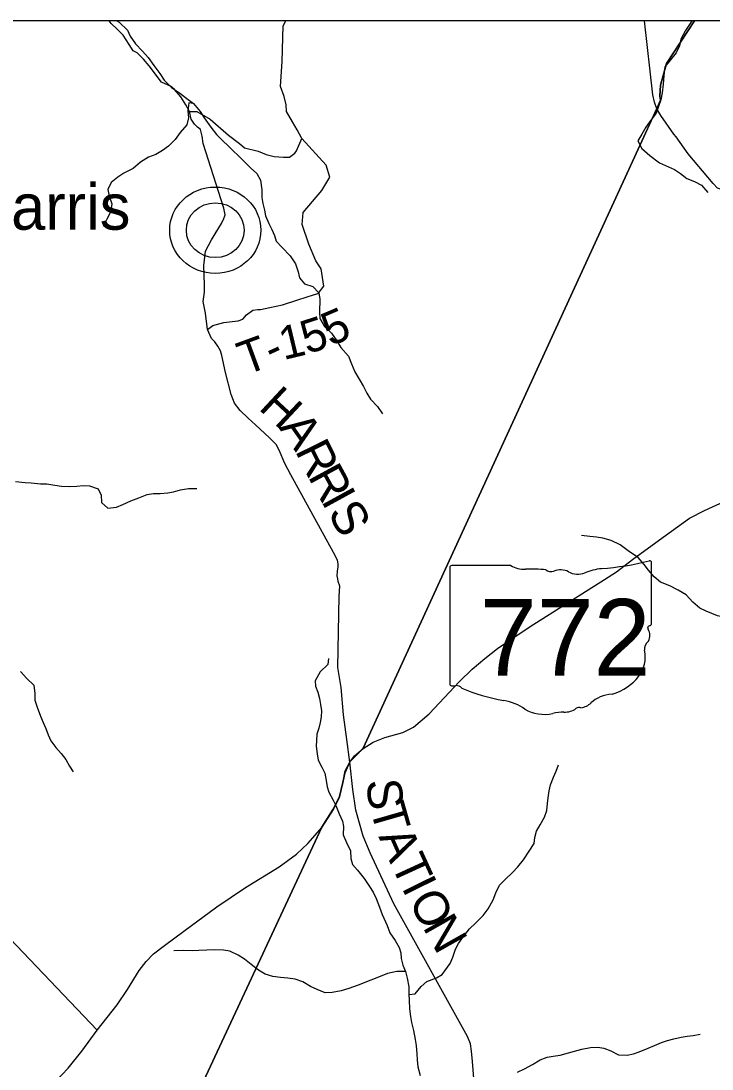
# Model space of a CAD drawing. Extents: x -139 to 835, y 0 to 440.
# Drawn here: x 168.3 to 206.1, y 344.1 to 401.5 of the extents above; entities that cross this region are included whole.
import ezdxf

# ---------------------------------------------------------------- set-up
doc = ezdxf.new("R2010")
doc.units = 0
for name, color, linetype in [('GM_X_County_Text', 7, 'Continuous'), ('GM_X_Minor_River', 7, 'Continuous'), ('GM_X_State_Location', 7, 'Continuous'), ('GM_X_State_Route', 7, 'Continuous'), ('GM_X_State_Shield', 7, 'Continuous'), ('GM_X_Township_Road', 7, 'Continuous'), ('GM_X_Township_Road_Text', 7, 'Continuous'), ('GM_X_Unincorporated', 7, 'Continuous'), ('GM_X_Unincorporated_Location', 7, 'Continuous'), ('GM_X_Unincorporated_Text', 7, 'Continuous'), ('SH_Cut_Line', 7, 'Continuous')]:
    doc.layers.add(name, color=color, linetype=linetype)

msp = doc.modelspace()

# ---------------------------------------------------------------- linework, layer by layer
at = {"layer": 'GM_X_County_Text'}
for points in [[(205.139, 401.486), (87.298, 401.486), (90.116, 391.109), (100.145, 354.177), (105.67, 333.828), (158.444, 330.1), (160.688, 329.921), (171.559, 329.033), (172.321, 330.669), (184.767, 357.384), (185.383, 358.364), (185.729, 359.048), (185.902, 359.821), (186.018, 360.334), (186.292, 360.95), (186.616, 361.275), (187.014, 361.689), (203.078, 396.689), (203.294, 397.153), (203.246, 397.371), (203.278, 397.973), (203.623, 399.152)], [(295.458, 319.381), (295.458, 401.486), (205.139, 401.486), (203.623, 399.152), (203.278, 397.973), (203.246, 397.371), (203.294, 397.153), (203.078, 396.689), (187.014, 361.689), (186.616, 361.275), (186.292, 360.95), (186.018, 360.334), (185.902, 359.821), (185.729, 359.048), (185.383, 358.364), (184.767, 357.384), (172.321, 330.669), (171.559, 329.033), (177.155, 328.576), (194.287, 327.176), (207.436, 326.102), (228.151, 324.569), (267.909, 321.538)]]:
    msp.add_lwpolyline(points, close=True, dxfattribs=at)
at = {"layer": 'GM_X_Minor_River'}
for points in [[(173.541, 401.486), (173.671, 401.418), (174.122, 400.991), (174.283, 400.663), (174.569, 400.238), (174.944, 399.836), (175.269, 399.483), (175.568, 399.057), (175.905, 398.607), (176.141, 398.243), (176.542, 397.841), (176.969, 397.546), (177.308, 397.301), (177.747, 396.971), (178.109, 396.533), (178.333, 396.192), (178.694, 395.67), (178.993, 395.269), (179.319, 394.939), (179.657, 394.634), (180.433, 393.878), (180.859, 393.451), (181.197, 393.146), (181.408, 392.782), (181.477, 392.25), (181.472, 391.828), (181.531, 391.49), (181.616, 391.14), (181.688, 390.825), (181.86, 390.401), (182.033, 390.074), (182.169, 389.747), (182.254, 389.444)], [(204.996, 401.486), (204.868, 401.284), (204.661, 400.961), (204.402, 400.494), (204.321, 400.121), (204.152, 399.749), (203.83, 399.367), (203.521, 398.972), (203.464, 398.503), (203.433, 398.033), (203.377, 397.551), (203.296, 397.166), (203.203, 396.854), (203.046, 396.433), (202.763, 396.051), (202.492, 395.68), (202.271, 395.284), (202.039, 394.925), (202.262, 394.501), (202.701, 394.122), (203.228, 393.73), (203.719, 393.508), (204.047, 393.359), (204.374, 393.139), (204.725, 392.869), (205.154, 392.696), (205.532, 392.511), (205.881, 392.097)], [(177.747, 396.971), (177.494, 397.01), (177.426, 396.577), (177.459, 396.19), (177.378, 395.805), (177.018, 395.387), (176.734, 394.993), (176.375, 394.635), (176.043, 394.398), (175.672, 394.185), (175.278, 394.032), (174.844, 393.76), (174.434, 393.415), (173.937, 393.167), (173.604, 392.942), (173.233, 392.657), (173.064, 392.261), (173.122, 391.898), (173.269, 391.487), (173.213, 391.053), (172.993, 390.646), (172.798, 390.238)], [(182.254, 389.444), (182.566, 389.103), (183.029, 388.64), (183.328, 388.19), (183.462, 387.755), (183.547, 387.44), (183.821, 387.099), (184.263, 386.95), (184.601, 386.608), (184.647, 386.258), (184.638, 385.547), (184.66, 385.209), (184.908, 384.772), (185.296, 384.406), (185.582, 383.993), (185.806, 383.617), (186.218, 383.154), (186.39, 382.718), (186.575, 382.294), (186.811, 381.893), (187.034, 381.493), (187.219, 381.117), (187.418, 380.789), (187.806, 380.399), (188.08, 379.986)], [(168.012, 376.281), (168.531, 376.227), (168.861, 376.223), (169.379, 376.169), (169.721, 376.153), (170.151, 376.088), (170.518, 376.036), (170.936, 376.007), (171.367, 376.038), (171.697, 376.07), (172.052, 376.054), (172.518, 375.88), (172.692, 375.541), (172.712, 375.131), (173.063, 374.837), (173.52, 374.88), (173.876, 375.021), (174.31, 375.233), (174.743, 375.397), (175.214, 375.573), (175.544, 375.629), (175.911, 375.637), (176.33, 375.669), (176.647, 375.725), (177.029, 375.83), (177.461, 375.909), (177.93, 375.904)], [(206.911, 368.826), (206.405, 368.941), (205.788, 369.201), (205.435, 369.361), (205.046, 369.679), (204.684, 370.093), (204.256, 370.339), (203.803, 370.585), (203.286, 370.784), (202.934, 371.078), (202.635, 371.431), (202.398, 371.747), (202.06, 372.124), (201.595, 372.431), (201.081, 372.822), (200.589, 373.057), (200.135, 373.195), (199.781, 373.247), (199.426, 373.275), (198.958, 373.329)], [(185.126, 366.611), (185.097, 366.274), (184.661, 365.869), (184.389, 365.39), (184.423, 365.088), (184.533, 364.761), (184.63, 364.411), (184.689, 364.085), (184.736, 363.746), (184.732, 363.409), (184.677, 363.096), (184.597, 362.783), (184.492, 362.459), (184.462, 362.122), (184.458, 361.808), (184.504, 361.386), (184.563, 361.048), (184.761, 360.66), (184.934, 360.332), (185.005, 359.934), (185.052, 359.583), (185.149, 359.281), (185.385, 358.856), (185.533, 358.553), (185.718, 358.105), (185.89, 357.705), (185.95, 357.403), (185.919, 356.958), (186.104, 356.533), (186.326, 356.073), (186.347, 355.663), (186.444, 355.324), (186.706, 355.02), (187.081, 354.569), (187.367, 354.12), (187.566, 353.817), (187.726, 353.477), (187.923, 352.993), (188.07, 352.593), (188.329, 352), (188.476, 351.588), (188.775, 351.175), (188.998, 350.799), (189.083, 350.496), (189.105, 350.195), (189.189, 349.832), (189.337, 349.481), (189.434, 349.118), (189.517, 348.647), (189.524, 348.225), (189.533, 347.911), (189.565, 347.429), (189.61, 347.007), (189.657, 346.693), (189.766, 346.257), (189.861, 345.762), (189.92, 345.436), (189.965, 344.977), (189.974, 344.64), (190.007, 344.266), (190.141, 343.794)], [(168.277, 365.897), (168.627, 365.507), (169.015, 365.153), (169.06, 364.682), (169.068, 364.32), (169.19, 363.945), (169.374, 363.449), (169.509, 363.11), (169.657, 362.771), (169.792, 362.431), (169.928, 362.104), (170.214, 361.727), (170.502, 361.411), (170.751, 361.07), (170.95, 360.718), (171.161, 360.403)], [(189.524, 348.225), (189.867, 348.257), (190.188, 348.664), (190.509, 348.937), (191.031, 349.136), (191.35, 349.314), (191.775, 349.912), (191.919, 350.26), (192.076, 350.692), (192.245, 351.015), (192.503, 351.398), (192.838, 351.816), (193.158, 352.114), (193.594, 352.543), (193.865, 352.902), (194.124, 353.405), (194.281, 353.789), (194.476, 354.197), (194.797, 354.519), (195.182, 354.888), (195.49, 355.198), (195.799, 355.581), (196.096, 356.06), (196.38, 356.478), (196.409, 356.816), (196.502, 357.152), (196.71, 357.511), (196.943, 357.931), (197.061, 358.291), (197.104, 358.664), (197.133, 358.977), (197.201, 359.363), (197.269, 359.687), (197.439, 360.107), (197.582, 360.431), (197.7, 360.78)], [(189.337, 349.481), (188.855, 349.474), (188.347, 349.371), (187.863, 349.172), (187.443, 348.996), (186.755, 348.738), (186.233, 348.551), (185.814, 348.423), (185.318, 348.321), (184.951, 348.313), (184.497, 348.486), (184.144, 348.659), (183.729, 348.917), (183.3, 349.054), (182.908, 349.119), (182.503, 349.148), (182.072, 349.201), (181.669, 349.338), (181.304, 349.559), (180.889, 349.853), (180.526, 350.146), (180.186, 350.379), (179.72, 350.589), (179.379, 350.654), (178.897, 350.659), (178.479, 350.64), (178.035, 350.621), (177.705, 350.612), (177.211, 350.618), (176.666, 350.6)], [(195.465, 343.963), (195.848, 344.152), (196.281, 344.388), (196.703, 344.649), (197.085, 344.789), (197.415, 344.845), (197.796, 344.902), (198.253, 345.029), (198.584, 345.11), (198.978, 345.226), (199.448, 345.317), (199.854, 345.336), (200.183, 345.285), (200.574, 345.135), (200.989, 344.914), (201.47, 344.896), (201.801, 344.977), (202.119, 345.082), (202.603, 345.281), (202.96, 345.434), (203.342, 345.599), (203.66, 345.704), (204.016, 345.796), (204.422, 345.876), (204.74, 345.933), (205.07, 345.977), (205.464, 346.045)]]:
    msp.add_lwpolyline(points, dxfattribs=at)
at = {"layer": 'GM_X_State_Route'}
for points in [[(186.299, 360.934), (186.549, 361.281), (187.021, 361.672), (187.569, 362.028), (188.215, 362.276), (189.19, 362.563), (189.767, 362.845), (190.629, 363.575), (192.288, 365.353), (192.993, 366.013), (193.672, 366.607), (194.369, 367.15), (196.158, 368.346), (200.223, 370.921), (200.884, 371.339), (201.748, 372.024), (203.24, 373.096), (204.869, 374.277), (205.689, 374.7), (209.356, 376.38)], [(169.456, 342.731), (169.842, 343.097), (170.891, 344.193), (171.641, 345.121), (172.478, 346.266), (173.572, 347.645), (174.127, 348.498), (174.762, 349.526), (175.158, 350.028), (175.555, 350.438), (176.146, 350.906), (177.213, 351.692), (179.011, 353.013), (180.58, 354.075), (182.432, 355.2), (183.384, 355.898), (183.99, 356.486), (184.774, 357.368), (185.39, 358.347), (185.737, 359.031), (185.909, 359.804), (186.029, 360.462), (186.299, 360.934)]]:
    msp.add_lwpolyline(points, dxfattribs=at)
at = {"layer": 'GM_X_State_Shield'}
for p, q in [((195.1, 371.689), (191.866, 371.689)), ((202.802, 368.52), (202.802, 371.846)), ((191.757, 371.579), (191.757, 365.22)), ((202.801, 368.52), (202.802, 368.52))]:
    msp.add_line(p, q, dxfattribs=at)
for centre, major_axis, start_param, end_param in [((191.883, 371.593), (0.128, 0), 1.712693, 3.28349), ((195.87, 372.427), (1.241, 0), 4.042523, 4.731795), ((198.867, 380.359), (11.713, 0), 4.814394, 5.042369), ((202.679, 371.86), (0.123, 0), 6.141152, 7.989035), ((196.282, 368.118), (4.455, 0), 1.404758, 1.657858), ((197.293, 371.626), (0.358, 0), 3.836095, 5.185415), ((197.819, 370.891), (0.744, 0), 0.950623, 2.079405), ((198.78, 371.899), (0.896, 0), 4.081561, 5.145723), ((200.361, 369.746), (2.356, 0), 1.699011, 2.107814), ((202.773, 368.275), (0.19, 0), 1.883978, 3.671073), ((201.563, 367.855), (1.142, 0), 5.934695, 6.695948), ((202.671, 368.507), (0.132, 0), 5.05454, 6.418171), ((199.524, 366.704), (2.93, 0), 5.101752, 6.440018), ((203.242, 367.127), (0.831, 0), 2.387724, 3.262537), ((191.885, 365.206), (0.129, 0), 3.00124, 4.508301), ((191.904, 365.856), (0.985, 0), 4.665946, 4.897461), ((192.106, 364.853), (0.355, 0), 0.519207, 1.627899), ((196.59, 370.567), (8.458, 0), 4.195997, 4.488961), ((194.069, 362.363), (2.646, 0), 0.823519, 1.323587), ((198.726, 364.603), (0.947, 0), 4.937069, 5.64225), ((200.759, 363.434), (1.605, 0), 1.647645, 2.488434), ((196.931, 364.821), (1.679, 0), 4.026481, 4.996735), ((197.901, 362.622), (1.38, 0), 1.495662, 1.94098), ((198.024, 364.345), (0.895, 0), 4.691044, 5.507374), ((198.833, 363.729), (0.252, 0), 1.147584, 2.315152)]:
    msp.add_ellipse(centre, major_axis=major_axis, ratio=0.758645, start_param=start_param, end_param=end_param, dxfattribs=at)
at = {"layer": 'GM_X_Township_Road'}
for points in [[(179.378, 390.628), (179.478, 390.886), (179.401, 391.251), (178.274, 394.788), (178.21, 395.177), (178.121, 395.542), (177.96, 395.679), (177.801, 395.841), (177.606, 396.113), (177.518, 396.526), (177.327, 396.894), (177.05, 397.338), (176.707, 397.734), (176.485, 397.91), (176.184, 398.04), (175.984, 398.143), (175.315, 399.032), (174.997, 399.392), (174.653, 399.741), (174.44, 399.856), (174.223, 400.201), (173.885, 400.718), (173.565, 401.042), (173.245, 401.341), (173.136, 401.486)], [(183.668, 395.062), (183.405, 395.529), (183.165, 395.959), (182.828, 396.537), (182.802, 396.9), (182.703, 397.362), (182.505, 397.9), (182.588, 399.263), (182.653, 401.218), (182.793, 401.486)], [(204.136, 395.143), (204.021, 395.301), (203.305, 396.32), (203.086, 396.672), (202.953, 397.038), (202.869, 397.437), (202.409, 401.486)], [(177.518, 396.526), (177.925, 396.538), (178.661, 396.118), (179.648, 395.243), (180.255, 394.79), (180.527, 394.54), (181.283, 394.36), (181.709, 394.178), (182.162, 394.068), (182.669, 394.029), (183, 394.043), (183.286, 394.252), (183.379, 394.382), (183.668, 395.062)], [(218.772, 383.829), (217.199, 384.253), (215.472, 385.041), (214.36, 385.594), (213.725, 385.975), (213.253, 386.279), (211.239, 388.369), (209.193, 390.665), (208.492, 391.35), (208.171, 391.626), (207.245, 392.04), (206.403, 392.331), (206.158, 392.592), (204.805, 394.222), (204.136, 395.143)], [(181.254, 385.692), (181.415, 385.706), (181.914, 385.812), (182.617, 385.948), (183.439, 386.225), (184.364, 386.524), (184.569, 386.578), (184.874, 386.98), (184.728, 387.927), (184.438, 388.37), (184.048, 389.276), (183.678, 390.35), (183.737, 391.001), (184.768, 392.202), (185.198, 392.939), (184.992, 393.597), (183.668, 395.062)], [(186.134, 362.165), (185.953, 363.52), (185.823, 365.025), (185.645, 366.117), (185.71, 370.017), (185.741, 370.56), (185.648, 370.816), (185.629, 370.96), (185.607, 371.132), (185.616, 371.385), (185.649, 371.614), (185.654, 371.783), (185.622, 371.977), (185.395, 372.406), (183.072, 376.656), (182.737, 377.282), (182.418, 378.004), (182.263, 378.311), (181.907, 378.684), (181.13, 379.396), (180.723, 379.758), (180.292, 380.17), (179.988, 380.577), (179.801, 381.054), (179.484, 382.248), (179.299, 383.183), (179.219, 383.44), (179.075, 383.685), (178.905, 383.932), (178.733, 384.106), (178.508, 384.597), (178.398, 385.494), (178.267, 386.138), (178.347, 386.643), (178.348, 387.054), (178.307, 388.106), (178.396, 388.889), (178.734, 389.519), (179.272, 390.409), (179.367, 390.6), (179.378, 390.628)], [(178.508, 384.597), (178.807, 384.817), (179.398, 384.993), (179.856, 385.039), (180.188, 385.078), (180.445, 385.179), (180.643, 385.403), (180.995, 385.67), (181.254, 385.692)], [(194.295, 327.159), (194.369, 327.701), (194.419, 328.371), (194.428, 328.995), (194.374, 329.583), (194.246, 330.318), (194.079, 331.912), (193.868, 333.247), (193.366, 339.941), (193.01, 344.553), (192.953, 345.122), (192.889, 345.511), (192.737, 345.914), (188.697, 353.173), (187.396, 355.966), (187.021, 356.883), (186.617, 358.306), (186.458, 359.442), (186.299, 360.934), (186.134, 362.165)], [(164.718, 354.383), (172.478, 346.266)]]:
    msp.add_lwpolyline(points, dxfattribs=at)
at = {"layer": 'GM_X_Unincorporated'}
for major_axis in [(2.493, 0), (1.581, 0)]:
    msp.add_ellipse((178.933, 390.036), major_axis=major_axis, ratio=0.948307, dxfattribs=at)
at = {"layer": 'GM_X_Unincorporated_Location'}
msp.add_line((178.933, 390.036), (178.933, 390.036), dxfattribs=at)
at = {"layer": 'SH_Cut_Line'}
msp.add_lwpolyline([(295.458, 319.381), (295.458, 401.486), (67.578, 401.486), (67.578, 336.518), (92.493, 334.759), (105.67, 333.828), (158.444, 330.1), (160.688, 329.921), (171.559, 329.033), (177.155, 328.576), (194.287, 327.176), (207.436, 326.102), (228.151, 324.569), (267.909, 321.538)], close=True, dxfattribs=at)

# ---------------------------------------------------------------- texts
at = {"layer": 'GM_X_State_Location'}
for s in ['s', 'r']:
    msp.add_text(s, height=0.00602, dxfattribs=at).set_placement((197.155, 367.977))
msp.add_text('772', height=0.00602, rotation=0.00001, dxfattribs=at).set_placement((194.915, 367.539))
at = {"layer": 'GM_X_State_Shield'}
msp.add_text('772', height=4.1897, dxfattribs=at).set_placement((193.399, 365.668))
at = {"layer": 'GM_X_Township_Road_Text'}
for s, height, rotation, p in [('5', 1.832, 22.99042, (185.23, 383.664)), ('1', 1.816, 13.51463, (182.663, 382.926)), ('5', 1.822, 17.89888, (183.95, 383.241)), ('T', 1.826, 20.14196, (180.578, 382.086)), ('-', 1.835, 24.73413, (182.062, 382.638)), ('H', 1.872, 317.02633, (181.25, 380.274)), ('A', 1.889, 305.12708, (182.38, 379.236)), ('R', 1.897, 296.51849, (183.273, 377.975)), ('R', 1.895, 298.53073, (183.973, 376.575)), ('I', 1.895, 298.70084, (184.693, 375.251)), ('S', 1.895, 298.69873, (185.053, 374.593)), ('S', 1.904, 276.86565, (187.175, 359.918)), ('T', 1.902, 286.0181, (187.381, 358.414)), ('A', 1.899, 293.98117, (187.845, 356.862)), ('T', 1.898, 294.64045, (188.506, 355.378)), ('I', 1.897, 296.55641, (189.101, 354.081)), ('O', 1.895, 298.50652, (189.467, 353.353)), ('N', 1.895, 299.4252, (190.249, 351.913))]:
    msp.add_text(s, height=height, rotation=rotation, dxfattribs=at).set_placement(p)
at = {"layer": 'GM_X_Unincorporated_Text'}
msp.add_text('Harris', height=2.5099, rotation=0.00001, dxfattribs=at).set_placement((165.341, 390.065))

doc.saveas('drawing.dxf')
